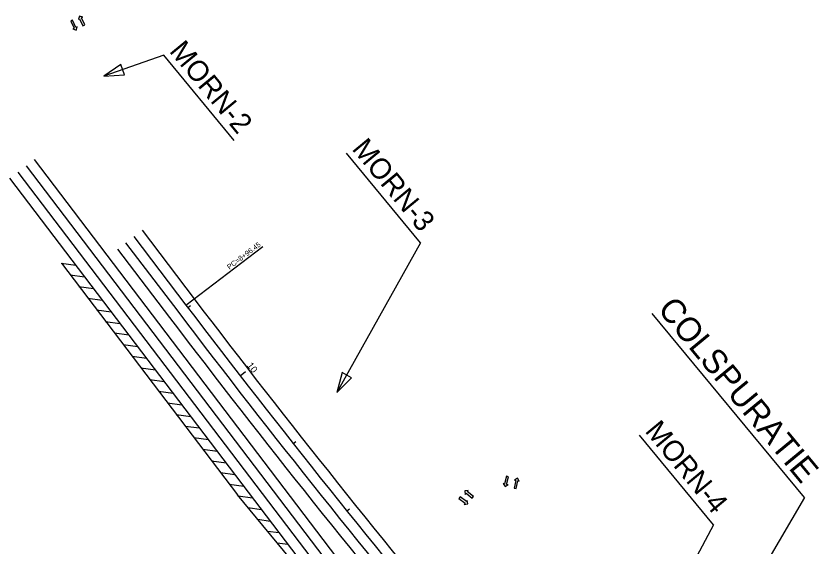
# Model space of a CAD drawing. Extents: x 1966356 to 1974207, y 790684 to 800034.
# Drawn here: x 1969541 to 1970474, y 797658 to 798275 of the extents above; entities that cross this region are included whole.
import ezdxf

# ---------------------------------------------------------------- set-up
doc = ezdxf.new("R2010")
doc.units = 0
for name, color, linetype in [('RD_EX_Pavement_Markings', 7, 'Continuous'), ('RD_HC_Cl', 7, 'Continuous'), ('RD_HC_Data', 7, 'Continuous'), ('RD_HC_Data_Tic', 7, 'Continuous'), ('RD_HC_TX_Sta50', 7, 'Continuous'), ('RD_PD_ALT5_LnLine', 7, 'Continuous'), ('RD_TX_RoadID', 7, 'Continuous')]:
    doc.layers.add(name, color=color, linetype=linetype)

msp = doc.modelspace()

# ---------------------------------------------------------------- linework, layer by layer
at = {"layer": 'RD_EX_Pavement_Markings'}
for p, q in [((1969562.52, 798108.19), (1969956.17, 797590.24)), ((1969552.97, 798100.93), (1969946.62, 797582.98)), ((1969543.41, 798093.67), (1969937.06, 797575.72)), ((1969687.78, 798026.01), (1969748.28, 797946.4)), ((1969678.22, 798018.75), (1969738.73, 797939.14)), ((1969668.67, 798011.49), (1969729.18, 797931.88)), ((1969659.11, 798004.23), (1969719.62, 797924.62))]:
    msp.add_line(p, q, dxfattribs=at)
at = {"layer": 'RD_HC_Cl'}
msp.add_arc((1978894.53, 804897.68), 11500, 217.235333, 219.93701, dxfattribs=at)
at = {"layer": 'RD_HC_Data'}
msp.add_line((1969738.73, 797939.14), (1969828.08, 798007.05), dxfattribs=at)
at = {"layer": 'RD_HC_Data_Tic'}
for p, q in [((1969740.88, 797936.31), (1969744.06, 797938.73)), ((1969801.76, 797856.98), (1969808.08, 797861.88)), ((1969863.33, 797778.18), (1969866.47, 797780.65)), ((1969925.57, 797699.92), (1969928.69, 797702.42))]:
    msp.add_line(p, q, dxfattribs=at)
at = {"layer": 'RD_PD_ALT5_LnLine'}
for p, q in [((1969533.98, 798086.5), (1969927.64, 797568.55)), ((1969593.97, 797987.74), (1969610.78, 797985.44)), ((1969594.03, 797987.65), (1969798.5, 797718.63)), ((1969604.24, 797974.22), (1969621.05, 797971.93)), ((1969614.51, 797960.71), (1969631.32, 797958.42)), ((1969624.78, 797947.2), (1969641.59, 797944.91)), ((1969635.04, 797933.69), (1969651.86, 797931.4)), ((1969645.31, 797920.18), (1969662.13, 797917.89)), ((1969655.58, 797906.67), (1969672.4, 797904.38)), ((1969665.85, 797893.16), (1969682.67, 797890.87)), ((1969676.12, 797879.65), (1969692.93, 797877.35)), ((1969686.39, 797866.14), (1969703.2, 797863.84)), ((1969696.66, 797852.62), (1969713.47, 797850.33)), ((1969706.93, 797839.11), (1969723.74, 797836.82)), ((1969717.2, 797825.6), (1969734.01, 797823.31)), ((1969727.46, 797812.09), (1969744.28, 797809.8)), ((1969737.73, 797798.58), (1969754.55, 797796.29)), ((1969748, 797785.07), (1969764.82, 797782.78)), ((1969758.27, 797771.56), (1969775.09, 797769.27)), ((1969768.54, 797758.05), (1969785.35, 797755.75)), ((1969778.81, 797744.54), (1969795.62, 797742.24)), ((1969789.08, 797731.02), (1969805.89, 797728.73)), ((1969982.7, 797496.42), (1969798.5, 797718.63)), ((1969799.43, 797717.5), (1969816.16, 797715.22)), ((1969810.75, 797703.85), (1969826.43, 797701.71)), ((1969822.07, 797690.19), (1969836.7, 797688.2)), ((1969833.39, 797676.54), (1969846.97, 797674.69)), ((1969844.71, 797662.88), (1969857.24, 797661.18))]:
    msp.add_line(p, q, dxfattribs=at)
for points in [[(1969607.09, 798270.13), (1969604.91, 798269.12), (1969608.76, 798260.8), (1969607.29, 798260.11), (1969611.04, 798258.74), (1969612.42, 798262.49), (1969610.94, 798261.81)], [(1969619.09, 798263.57), (1969621.27, 798264.58), (1969617.42, 798272.9), (1969618.89, 798273.59), (1969615.14, 798274.96), (1969613.76, 798271.21), (1969615.24, 798271.89)], [(1970113.3, 797739.71), (1970110.96, 797740.24), (1970108.91, 797731.3), (1970107.32, 797731.66), (1970109.45, 797728.28), (1970112.84, 797730.4), (1970111.25, 797730.77)], [(1970119.82, 797726.39), (1970122.16, 797725.85), (1970124.21, 797734.79), (1970125.8, 797734.43), (1970123.67, 797737.82), (1970120.28, 797735.69), (1970121.87, 797735.33)], [(1970057.25, 797716.33), (1970055.79, 797714.43), (1970063.06, 797708.84), (1970062.07, 797707.55), (1970066.04, 797708.07), (1970065.52, 797712.04), (1970064.53, 797710.75)], [(1970071.34, 797714.88), (1970072.8, 797716.78), (1970065.52, 797722.37), (1970066.51, 797723.66), (1970062.55, 797723.14), (1970063.07, 797719.17), (1970064.06, 797720.46)]]:
    msp.add_lwpolyline(points, close=True, dxfattribs=at)
for radius in [11488, 11512, 11500, 11524]:
    msp.add_arc((1978894.53, 804897.68), radius, 217.235333, 219.93701, dxfattribs=at)
at = {"layer": 'RD_TX_RoadID'}
for p, q in [((1969794.87, 798130.52), (1969713.17, 798229.44)), ((1970011.29, 798011.58), (1969925.23, 798115.79)), ((1970457.1, 797715.36), (1970280.25, 797929.49)), ((1970351.65, 797683.74), (1970265.58, 797787.95))]:
    msp.add_line(p, q, dxfattribs=at)
for points in [[(1969713.17, 798229.44), (1969643.34, 798204.99)], [(1970011.29, 798011.58), (1969914.15, 797837.4)], [(1970457.1, 797715.36), (1970283.52, 797418.13)], [(1970351.65, 797683.74), (1970279.73, 797548.86)]]:
    msp.add_lwpolyline(points, dxfattribs=at)
for points in [[(1969663.17, 798218.51), (1969643.34, 798204.99), (1969667.28, 798206.79)], [(1969920.02, 797860.67), (1969914.15, 797837.4), (1969930.87, 797854.62)]]:
    msp.add_lwpolyline(points, close=True, dxfattribs=at)

# ---------------------------------------------------------------- texts
at = {"layer": 'RD_HC_Data'}
msp.add_text('PC=8+96.45', height=6, rotation=37.23533, dxfattribs=at).set_placement((1969789.27, 797980.06))
at = {"layer": 'RD_HC_TX_Sta50'}
msp.add_text('10', height=8, rotation=307.75125, dxfattribs=at).set_placement((1969809.04, 797868.81))
at = {"layer": 'RD_TX_RoadID'}
for s, height, p in [('MORN-2', 24, (1969718.57, 798233.9)), ('MORN-3 ', 24, (1969930.63, 798120.25)), ('COLSPURATIE', 28, (1970285.65, 797933.95)), ('MORN-4 ', 24, (1970270.98, 797792.41))]:
    msp.add_text(s, height=height, rotation=309.55175, dxfattribs=at).set_placement(p)

doc.saveas('drawing.dxf')
